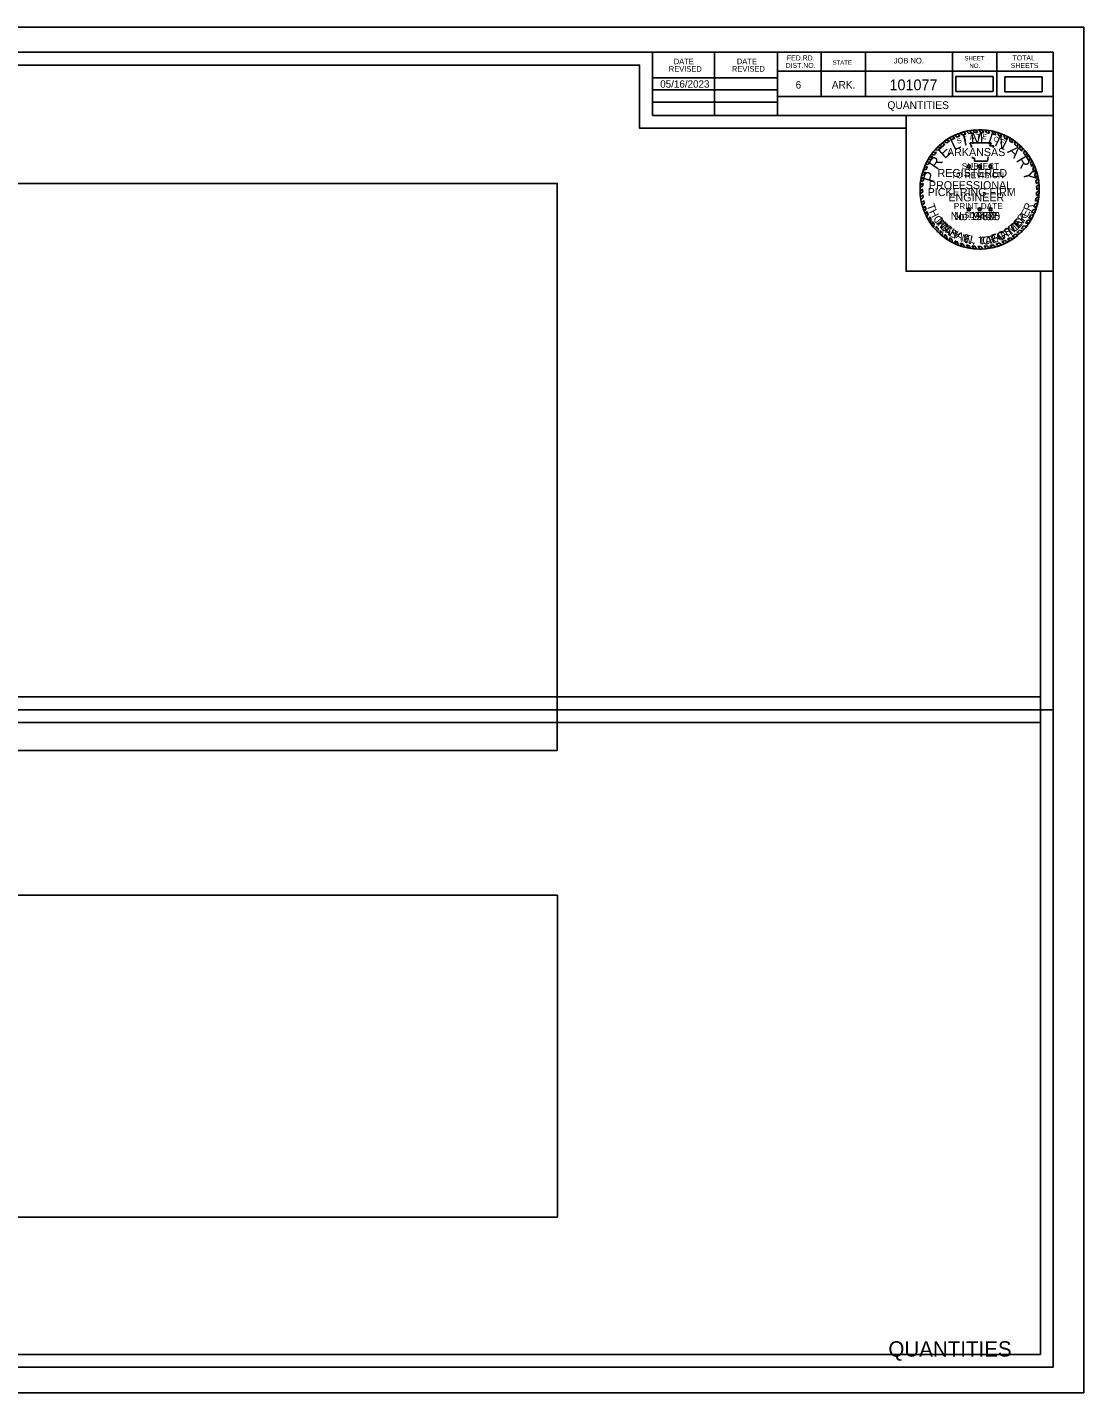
# Model space of a CAD drawing. Extents: x 1369655 to 1370989, y 380216 to 380430.
# Drawn here: x 1369823.5 to 1369988.6, y 380216.4 to 380429.8 of the extents above; entities that cross this region are included whole.
import ezdxf

# ---------------------------------------------------------------- set-up
doc = ezdxf.new("R2010")
doc.units = 0
for name, color, linetype in [('Default', 7, 'Continuous'), ('R_Border', 7, 'Continuous'), ('R_Border Notes', 7, 'Continuous'), ('R_Border Plan-Plan', 7, 'Continuous'), ('R_Border Title', 7, 'Continuous'), ('R_No Plot', 7, 'Continuous'), ('R_Revision Date Text', 7, 'Continuous'), ('STAMP_PE_CRAFTON', 7, 'Continuous'), ('STAMP_PE_FOSTER', 7, 'Continuous'), ('STAMP_PE_SEAL-INFO', 7, 'Continuous'), ('STAMP_PE_TAEGTMEYER', 7, 'Continuous'), ('STAMP_PE_TXT', 7, 'Continuous'), ('STAMP_PRELIMINARY', 7, 'Continuous')]:
    doc.layers.add(name, color=color, linetype=linetype)

msp = doc.modelspace()

# ---------------------------------------------------------------- linework, layer by layer
at = {"layer": 'Default'}
for points in [[(1369968.59, 380419.74), (1369974.42, 380419.74), (1369974.42, 380422.05), (1369968.59, 380422.05)], [(1369976.26, 380419.69), (1369982.09, 380419.69), (1369982.09, 380422), (1369976.26, 380422)], [(1369745.17, 380316.79), (1369906.32, 380316.79), (1369906.32, 380405.38), (1369745.17, 380405.38)], [(1369746.53, 380243.85), (1369906.34, 380243.85), (1369906.34, 380294.16), (1369746.53, 380294.16)]]:
    msp.add_lwpolyline(points, close=True, dxfattribs=at)
at = {"layer": 'R_Border'}
for p, q in [((1369667.65, 380425.87), (1369983.83, 380425.87)), ((1369921.19, 380415.99), (1369921.19, 380425.87)), ((1369930.87, 380415.99), (1369930.87, 380425.87)), ((1369940.73, 380425.87), (1369940.73, 380415.99)), ((1369947.57, 380425.87), (1369947.57, 380418.93)), ((1369954.51, 380425.87), (1369954.51, 380418.93)), ((1369968.09, 380425.87), (1369968.09, 380418.93)), ((1369975.03, 380425.87), (1369975.03, 380418.93)), ((1369983.83, 380220.41), (1369983.83, 380425.87)), ((1369921.19, 380421.85), (1369940.73, 380421.85)), ((1369983.83, 380422.93), (1369940.73, 380422.93)), ((1369983.83, 380422.95), (1369983.83, 380422.95)), ((1369921.19, 380419.99), (1369940.73, 380419.99)), ((1369921.19, 380418.05), (1369940.73, 380418.05)), ((1369983.83, 380418.93), (1369940.73, 380418.93)), ((1369943.69, 380418.93), (1369983.83, 380418.93)), ((1369983.83, 380415.99), (1369921.19, 380415.99)), ((1369983.83, 380220.41), (1369667.65, 380220.41))]:
    msp.add_line(p, q, dxfattribs=at)
at = {"layer": 'R_Border Plan-Plan'}
msp.add_line((1369667.65, 380323.14), (1369983.83, 380323.14), dxfattribs=at)
at = {"layer": 'R_No Plot'}
for points in [[(1369655.25, 380429.76), (1369988.59, 380429.76), (1369988.59, 380216.42), (1369655.25, 380216.42)], [(1369981.83, 380325.14), (1369669.65, 380325.14), (1369669.65, 380423.87), (1369919.19, 380423.87), (1369919.19, 380413.99), (1369936.73, 380413.99), (1369960.83, 380413.99), (1369960.83, 380391.65), (1369981.83, 380391.65)], [(1369669.65, 380423.87), (1369919.19, 380423.87), (1369919.19, 380413.99), (1369936.73, 380413.99), (1369960.83, 380413.99), (1369960.83, 380391.65), (1369981.83, 380391.65), (1369981.83, 380222.41), (1369669.65, 380222.41)], [(1369960.83, 380415.99), (1369983.83, 380415.99), (1369983.83, 380391.65), (1369960.83, 380391.65)], [(1369669.65, 380321.14), (1369981.83, 380321.14), (1369981.83, 380222.41), (1369669.65, 380222.41)]]:
    msp.add_lwpolyline(points, close=True, dxfattribs=at)
at = {"layer": 'STAMP_PE_SEAL-INFO'}
for p, q in [((1369968.95, 380413.12), (1369969.24, 380412.79)), ((1369969.29, 380413.24), (1369969.67, 380412.94)), ((1369969.88, 380413.43), (1369970.17, 380413.08)), ((1369970.27, 380413.52), (1369970.63, 380413.18)), ((1369970.75, 380413.62), (1369971.05, 380413.25)), ((1369971.27, 380413.69), (1369971.55, 380413.31)), ((1369972.01, 380413.34), (1369971.69, 380413.73)), ((1369972.5, 380413.34), (1369972.22, 380413.75)), ((1369972.96, 380413.32), (1369972.7, 380413.75)), ((1369973.47, 380413.27), (1369973.18, 380413.71)), ((1369973.89, 380413.21), (1369973.64, 380413.66)), ((1369974.46, 380413.09), (1369974.28, 380413.55)), ((1369974.86, 380412.98), (1369974.7, 380413.45)), ((1369975.31, 380412.83), (1369975.17, 380413.31)), ((1369975.73, 380412.67), (1369975.58, 380413.17)), ((1369976.19, 380412.47), (1369976.09, 380412.96)), ((1369965.7, 380410.98), (1369966.24, 380410.93)), ((1369966.03, 380411.3), (1369966.49, 380411.16)), ((1369966.37, 380411.6), (1369966.9, 380411.5)), ((1369966.75, 380411.93), (1369967.21, 380411.72)), ((1369967.17, 380412.19), (1369967.61, 380411.99)), ((1369967.56, 380412.44), (1369967.99, 380412.21)), ((1369968.01, 380412.69), (1369968.47, 380412.46)), ((1369968.44, 380412.9), (1369968.83, 380412.62)), ((1369970.81, 380411.72), (1369974.15, 380411.72)), ((1369970.93, 380411.41), (1369970.81, 380411.72)), ((1369971.03, 380411.12), (1369970.93, 380411.41)), ((1369971.04, 380411), (1369971.03, 380411.12)), ((1369974.15, 380411.72), (1369973.93, 380411.23)), ((1369973.93, 380411.23), (1369974.56, 380411.23)), ((1369974.56, 380411.23), (1369974.41, 380411)), ((1369976.63, 380412.24), (1369976.55, 380412.75)), ((1369977.02, 380412.01), (1369976.98, 380412.51)), ((1369977.46, 380411.72), (1369977.42, 380412.24)), ((1369977.82, 380411.46), (1369977.85, 380411.94)), ((1369978.26, 380411.09), (1369978.28, 380411.61)), ((1369978.58, 380410.79), (1369978.65, 380411.29)), ((1369978.93, 380410.42), (1369979, 380410.95)), ((1369964.04, 380408.68), (1369964.54, 380408.75)), ((1369964.27, 380409.11), (1369964.76, 380409.13)), ((1369964.51, 380409.51), (1369965.03, 380409.54)), ((1369964.75, 380409.85), (1369965.25, 380409.85)), ((1369965.03, 380410.22), (1369965.58, 380410.24)), ((1369965.37, 380410.63), (1369965.89, 380410.59)), ((1369971.23, 380409.29), (1369971.2, 380409.51)), ((1369971.54, 380409.29), (1369971.23, 380409.29)), ((1369971.54, 380408.86), (1369971.54, 380409.29)), ((1369973.57, 380408.86), (1369971.54, 380408.86)), ((1369973.59, 380409.2), (1369973.57, 380408.86)), ((1369973.67, 380409.51), (1369973.59, 380409.2)), ((1369979.21, 380410.1), (1369979.35, 380410.57)), ((1369979.53, 380409.69), (1369979.67, 380410.19)), ((1369979.75, 380409.37), (1369979.93, 380409.83)), ((1369980.06, 380408.87), (1369980.24, 380409.36)), ((1369980.26, 380408.51), (1369980.49, 380408.95)), ((1369963.25, 380406.54), (1369963.72, 380406.74)), ((1369963.36, 380406.95), (1369963.84, 380407.12)), ((1369963.52, 380407.45), (1369964, 380407.59)), ((1369963.67, 380407.86), (1369964.17, 380408.01)), ((1369963.85, 380408.29), (1369964.35, 380408.4)), ((1369980.49, 380408.02), (1369980.72, 380408.51)), ((1369980.63, 380407.69), (1369980.9, 380408.12)), ((1369980.83, 380407.14), (1369981.1, 380407.61)), ((1369980.93, 380406.77), (1369981.23, 380407.22)), ((1369981.07, 380406.21), (1369981.39, 380406.66)), ((1369963.44, 380404.98), (1369963.02, 380404.72)), ((1369963.42, 380404.49), (1369963.02, 380404.15)), ((1369963.47, 380405.4), (1369963.04, 380405.12)), ((1369963.53, 380405.84), (1369963.09, 380405.62)), ((1369963.62, 380406.3), (1369963.15, 380406.05)), ((1369981.14, 380405.83), (1369981.49, 380406.19)), ((1369981.2, 380405.32), (1369981.57, 380405.66)), ((1369981.23, 380404.91), (1369981.62, 380405.2)), ((1369981.25, 380404.39), (1369981.65, 380404.71)), ((1369963.43, 380404.08), (1369963.04, 380403.75)), ((1369963.46, 380403.58), (1369963.09, 380403.23)), ((1369963.51, 380403.15), (1369963.16, 380402.78)), ((1369963.59, 380402.69), (1369963.25, 380402.33)), ((1369963.68, 380402.28), (1369963.37, 380401.86)), ((1369980.95, 380402.14), (1369981.42, 380402.34)), ((1369981.06, 380402.59), (1369981.51, 380402.78)), ((1369981.15, 380403.09), (1369981.59, 380403.31)), ((1369981.2, 380403.48), (1369981.63, 380403.73)), ((1369981.24, 380403.98), (1369981.66, 380404.26)), ((1369963.81, 380401.83), (1369963.51, 380401.41)), ((1369963.95, 380401.41), (1369963.67, 380400.99)), ((1369964.12, 380400.98), (1369963.85, 380400.56)), ((1369964.29, 380400.6), (1369964.06, 380400.13)), ((1369980.29, 380400.41), (1369980.78, 380400.48)), ((1369980.45, 380400.75), (1369980.94, 380400.84)), ((1369980.67, 380401.26), (1369981.15, 380401.39)), ((1369980.8, 380401.64), (1369981.29, 380401.84)), ((1369964.52, 380400.14), (1369964.33, 380399.65)), ((1369964.76, 380399.73), (1369964.57, 380399.26)), ((1369964.96, 380399.42), (1369964.85, 380398.87)), ((1369965.24, 380399.03), (1369965.14, 380398.5)), ((1369965.54, 380398.65), (1369965.46, 380398.13)), ((1369965.85, 380398.32), (1369965.79, 380397.79)), ((1369978.56, 380398.05), (1369979, 380397.91)), ((1369978.82, 380398.31), (1369979.29, 380398.23)), ((1369979.2, 380398.74), (1369979.66, 380398.67)), ((1369979.51, 380399.14), (1369980.01, 380399.14)), ((1369979.85, 380399.63), (1369980.32, 380399.63)), ((1369980.02, 380399.91), (1369980.52, 380399.97)), ((1369966.17, 380397.99), (1369966.14, 380397.46)), ((1369966.51, 380397.68), (1369966.51, 380397.15)), ((1369966.87, 380397.38), (1369966.89, 380396.86)), ((1369967.21, 380397.13), (1369967.25, 380396.62)), ((1369967.64, 380396.85), (1369967.7, 380396.34)), ((1369967.99, 380396.65), (1369968.08, 380396.13)), ((1369968.47, 380396.4), (1369968.63, 380395.88)), ((1369968.84, 380396.23), (1369969.02, 380395.72)), ((1369969.34, 380396.04), (1369969.55, 380395.53)), ((1369969.75, 380395.9), (1369969.97, 380395.41)), ((1369974.89, 380395.89), (1369975.3, 380395.59)), ((1369975.38, 380396.05), (1369975.82, 380395.78)), ((1369975.8, 380396.22), (1369976.22, 380395.96)), ((1369976.26, 380396.43), (1369976.74, 380396.22)), ((1369976.67, 380396.64), (1369977.08, 380396.41)), ((1369977.08, 380396.89), (1369977.53, 380396.69)), ((1369977.42, 380397.11), (1369977.86, 380396.92)), ((1369977.88, 380397.46), (1369978.35, 380397.31)), ((1369978.16, 380397.68), (1369978.63, 380397.55)), ((1369970.25, 380395.76), (1369970.47, 380395.3)), ((1369970.65, 380395.68), (1369970.9, 380395.22)), ((1369971.15, 380395.6), (1369971.39, 380395.16)), ((1369971.59, 380395.55), (1369971.86, 380395.12)), ((1369972.07, 380395.52), (1369972.38, 380395.11)), ((1369972.53, 380395.52), (1369972.88, 380395.12)), ((1369973.05, 380395.55), (1369973.38, 380395.17)), ((1369973.49, 380395.59), (1369973.86, 380395.23)), ((1369973.93, 380395.66), (1369974.32, 380395.32)), ((1369974.43, 380395.77), (1369974.8, 380395.44))]:
    msp.add_line(p, q, dxfattribs=at)
for radius, start, end in [(9.32, 111.3124, 114.7026), (9.32, 105.2339, 109.0352), (8.91, 104.0352, 107.3615), (9.32, 99.7525, 102.7765), (8.91, 98.258, 101.0329), (9.32, 93.9381, 96.5517), (8.91, 92.1102, 95.0367), (9.32, 87.7298, 90.6707), (8.91, 85.9628, 88.9097), (9.32, 81.9732, 84.8236), (8.91, 79.9264, 82.696), (9.32, 75.3125, 77.9426), (8.91, 73.5575, 76.2314), (9.32, 69.6061, 72.3058), (9.32, 63.1329, 66.2704), (9.32, 135.4021, 138.3031), (8.91, 133.1331, 136.2562), (9.32, 129.7326, 132.5376), (8.91, 127.5297, 130.9683), (9.32, 123.6199, 126.5906), (8.91, 121.9746, 125.11), (9.32, 117.6544, 120.8099), (8.91, 115.6869, 119.1583), (8.91, 110.3086, 113.1659), (8.91, 67.6248, 70.504), (8.91, 61.1558, 64.3784), (9.32, 56.9003, 60.0942), (8.91, 54.9238, 58.2702), (8.91, 48.3016, 52.0395), (9.32, 50.3492, 53.7159), (9.32, 44.3405, 47.3929), (9.32, 152.864, 155.5189), (9.32, 147.0072, 149.899), (8.91, 151.0315, 153.573), (9.32, 141.6056, 144.4486), (8.91, 145.0197, 148.2104), (8.91, 139.301, 142.5873), (8.91, 42.2212, 45.5512), (8.91, 36.135, 39.5311), (9.32, 38.1247, 41.2316), (8.91, 29.9032, 33.6645), (9.32, 31.9614, 35.4294), (9.32, 25.9391, 29.0125), (9.32, 164.3068, 166.894), (9.32, 158.4077, 161.0701), (8.91, 162.4331, 165.0013), (8.91, 156.3402, 159.2319), (8.91, 23.7732, 27.2211), (8.91, 17.6802, 21.4251), (9.32, 19.9538, 23.3141), (8.91, 11.5444, 15.2364), (9.32, 13.8421, 17.4447), (9.32, 175.7409, 178.2066), (9.32, 170.0003, 172.6878), (8.91, 179.6454, 182.2633), (8.91, 173.73, 176.4734), (8.91, 167.9048, 170.9039), (8.91, 5.7599, 9.0606), (8.91, 359.7329, 3.0639), (9.32, 7.5852, 10.8621), (9.32, 1.7215, 4.7268), (9.32, 181.7251, 184.1626), (9.32, 187.4204, 190.1927), (9.32, 193.0369, 195.9973), (8.91, 185.4539, 188.234), (8.91, 191.2274, 193.9858), (8.91, 348.0778, 351.3435), (8.91, 353.8632, 357.1274), (9.32, 343.8925, 347.035), (9.32, 349.8305, 353.0885), (9.32, 355.7156, 358.9569), (9.32, 198.8967, 201.6281), (8.91, 196.9675, 199.8353), (9.32, 204.5479, 207.4328), (8.91, 202.7761, 205.4791), (8.91, 329.5549, 333.2076), (8.91, 335.6038, 339.1858), (9.32, 331.4037, 334.9332), (8.91, 341.777, 345.0925), (9.32, 337.3837, 340.9933), (9.32, 210.8636, 213.6571), (8.91, 208.7883, 211.7934), (9.32, 216.6115, 219.491), (8.91, 214.1838, 217.2747), (9.32, 222.48, 225.3801), (8.91, 220.3909, 223.3056), (8.91, 310.7744, 314.3161), (8.91, 316.6531, 320.3711), (9.32, 318.2846, 321.8043), (8.91, 323.5851, 327.4407), (9.32, 325.4405, 328.9872), (9.32, 228.3665, 231.348), (8.91, 226.2494, 229.2407), (8.91, 232.229, 234.9336), (9.32, 234.295, 236.9452), (8.91, 238.2223, 240.8353), (9.32, 240.1977, 242.8613), (8.91, 244.3204, 246.9486), (9.32, 246.576, 249.1558), (8.91, 250.3491, 253.1216), (8.91, 286.6423, 289.9783), (8.91, 292.8745, 296.1185), (9.32, 294.6481, 298.2166), (8.91, 299.0768, 302.1724), (9.32, 300.621, 303.8703), (8.91, 304.823, 308.5143), (9.32, 306.3721, 310.208), (9.32, 312.4518, 315.6633), (9.32, 252.5967, 255.3252), (8.91, 256.505, 259.1192), (9.32, 258.4433, 261.1398), (8.91, 262.3783, 265.2012), (9.32, 264.1978, 267.1009), (8.91, 268.3215, 271.277), (9.32, 270.2548, 273.3361), (8.91, 274.6157, 277.4486), (9.32, 276.4239, 279.4357), (8.91, 280.3459, 283.5814), (9.32, 282.3199, 285.3702), (9.32, 288.5709, 291.9733)]:
    msp.add_arc((1369972.33, 380404.43), radius, start, end, dxfattribs=at)
at = {"layer": 'STAMP_PE_TXT'}
for p, q in [((1369970.51, 380408), (1369970.31, 380408.15)), ((1369970.31, 380408.15), (1369970.56, 380408.15)), ((1369970.44, 380407.77), (1369970.51, 380408)), ((1369970.64, 380407.91), (1369970.44, 380407.77)), ((1369970.56, 380408.15), (1369970.64, 380408.38)), ((1369970.64, 380408.38), (1369970.71, 380408.15)), ((1369970.83, 380407.77), (1369970.64, 380407.91)), ((1369970.71, 380408.15), (1369970.96, 380408.15)), ((1369970.96, 380408.15), (1369970.76, 380408)), ((1369970.76, 380408), (1369970.83, 380407.77)), ((1369972.21, 380408), (1369972.01, 380408.15)), ((1369972.01, 380408.15), (1369972.26, 380408.15)), ((1369972.14, 380407.77), (1369972.21, 380408)), ((1369972.33, 380407.91), (1369972.14, 380407.77)), ((1369972.26, 380408.15), (1369972.33, 380408.38)), ((1369972.33, 380408.38), (1369972.41, 380408.15)), ((1369972.53, 380407.77), (1369972.33, 380407.91)), ((1369972.41, 380408.15), (1369972.65, 380408.15)), ((1369972.65, 380408.15), (1369972.46, 380408)), ((1369972.46, 380408), (1369972.53, 380407.77)), ((1369973.91, 380408), (1369973.71, 380408.15)), ((1369973.71, 380408.15), (1369973.96, 380408.15)), ((1369973.83, 380407.77), (1369973.91, 380408)), ((1369974.03, 380407.91), (1369973.83, 380407.77)), ((1369973.96, 380408.15), (1369974.03, 380408.38)), ((1369974.03, 380408.38), (1369974.11, 380408.15)), ((1369974.23, 380407.77), (1369974.03, 380407.91)), ((1369974.11, 380408.15), (1369974.35, 380408.15)), ((1369974.35, 380408.15), (1369974.15, 380408)), ((1369974.15, 380408), (1369974.23, 380407.77)), ((1369970.51, 380401.29), (1369970.31, 380401.44)), ((1369970.31, 380401.44), (1369970.56, 380401.44)), ((1369970.44, 380401.06), (1369970.51, 380401.29)), ((1369970.64, 380401.21), (1369970.44, 380401.06)), ((1369970.56, 380401.44), (1369970.64, 380401.67)), ((1369970.64, 380401.67), (1369970.71, 380401.44)), ((1369970.83, 380401.06), (1369970.64, 380401.21)), ((1369970.71, 380401.44), (1369970.96, 380401.44)), ((1369970.96, 380401.44), (1369970.76, 380401.29)), ((1369970.76, 380401.29), (1369970.83, 380401.06)), ((1369972.21, 380401.29), (1369972.01, 380401.44)), ((1369972.01, 380401.44), (1369972.26, 380401.44)), ((1369972.14, 380401.06), (1369972.21, 380401.29)), ((1369972.33, 380401.21), (1369972.14, 380401.06)), ((1369972.26, 380401.44), (1369972.33, 380401.67)), ((1369972.33, 380401.67), (1369972.41, 380401.44)), ((1369972.53, 380401.06), (1369972.33, 380401.21)), ((1369972.41, 380401.44), (1369972.65, 380401.44)), ((1369972.65, 380401.44), (1369972.46, 380401.29)), ((1369972.46, 380401.29), (1369972.53, 380401.06)), ((1369973.91, 380401.29), (1369973.71, 380401.44)), ((1369973.71, 380401.44), (1369973.96, 380401.44)), ((1369973.83, 380401.06), (1369973.91, 380401.29)), ((1369974.03, 380401.21), (1369973.83, 380401.06)), ((1369973.96, 380401.44), (1369974.03, 380401.67)), ((1369974.03, 380401.67), (1369974.11, 380401.44)), ((1369974.23, 380401.06), (1369974.03, 380401.21)), ((1369974.11, 380401.44), (1369974.35, 380401.44)), ((1369974.35, 380401.44), (1369974.15, 380401.29)), ((1369974.15, 380401.29), (1369974.23, 380401.06))]:
    msp.add_line(p, q, dxfattribs=at)
at = {"layer": 'STAMP_PRELIMINARY'}
msp.add_circle((1369972.33, 380404.43), 9.32, dxfattribs=at)

# ---------------------------------------------------------------- texts
at = {"layer": 'R_Border'}
for s, height, p in [('REVISED', 0.879, (1369923.75, 380422.82)), ('DATE', 0.879, (1369924.53, 380424)), ('REVISED', 0.879, (1369933.61, 380422.82)), ('DATE', 0.879, (1369934.39, 380424)), ('DIST.NO.', 0.782, (1369942.01, 380423.41)), ('FED.RD.', 0.782, (1369942.21, 380424.59)), ('STATE', 0.684, (1369949.33, 380423.91)), ('JOB NO.', 0.879, (1369958.91, 380424.11)), ('SHEET', 0.684, (1369969.95, 380424.59)), ('NO.', 0.684, (1369970.73, 380423.41)), ('SHEETS', 0.782, (1369977.19, 380423.41)), ('TOTAL', 0.782, (1369977.47, 380424.59)), ('6', 1.17, (1369943.57, 380420.19)), ('ARK.', 1.172, (1369949.23, 380420.19))]:
    msp.add_text(s, height=height, dxfattribs=at).set_placement(p)
at = {"layer": 'R_Border Notes'}
for s, height, p in [('101077', 1.68, (1369958.24, 380419.93)), ('QUANTITIES', 1.2, (1369957.91, 380417.01))]:
    msp.add_text(s, height=height, dxfattribs=at).set_placement(p)
at = {"layer": 'R_Border Title'}
msp.add_text('QUANTITIES', height=2.4, dxfattribs=at).set_placement((1369958.07, 380222.06))
at = {"layer": 'R_Revision Date Text'}
msp.add_text('05/16/2023', height=1.15, dxfattribs=at).set_placement((1369922.41, 380420.33))
at = {"layer": 'STAMP_PE_CRAFTON'}
msp.add_text('No. 12370', height=1.25, dxfattribs=at).set_placement((1369967.8, 380399.63))
for s, rotation, p in [('T', 310.7442, (1369965.3, 380399.33)), ('O', 317.6422, (1369965.97, 380398.52)), ('N', 324.4537, (1369966.81, 380397.73)), ('Y', 331.1686, (1369967.85, 380397.02)), ('F', 28.7821, (1369975.99, 380396.56)), ('T', 34.1136, (1369976.91, 380397.07)), ('O', 41.8391, (1369977.77, 380397.67)), ('N', 49.2411, (1369978.62, 380398.45)), ('N', 347.4752, (1369969.9, 380396.1)), ('.', 356.8926, (1369971.13, 380395.82)), ('C', 6.0117, (1369972.81, 380395.77)), ('R', 14.8189, (1369973.9, 380395.89)), ('A', 20.5125, (1369975.01, 380396.19))]:
    msp.add_text(s, height=1.25, rotation=rotation, dxfattribs=at).set_placement(p)
at = {"layer": 'STAMP_PE_FOSTER'}
msp.add_text('No. 9402', height=1.25, dxfattribs=at).set_placement((1369968.32, 380399.63))
for s, rotation, p in [('R', 54.5031, (1369979.06, 380399.24)), ('M', 308.339, (1369965.45, 380399.45)), ('I', 314.1842, (1369966.25, 380398.51)), ('C', 319.8733, (1369966.6, 380398.16)), ('H', 327.7235, (1369967.53, 380397.42)), ('S', 31.7234, (1369976.52, 380397.04)), ('T', 39.4194, (1369977.48, 380397.67)), ('E', 46.9613, (1369978.33, 380398.42)), ('A', 335.7276, (1369968.51, 380396.84)), ('E', 343.5779, (1369969.65, 380396.37)), ('L', 350.8115, (1369970.71, 380396.1)), ('L', 1.2666, (1369972.25, 380395.94)), ('.', 6.8035, (1369973.29, 380396)), ('F', 15.8691, (1369974.37, 380396.18)), ('O', 23.719, (1369975.41, 380396.51))]:
    msp.add_text(s, height=1.2, rotation=rotation, dxfattribs=at).set_placement(p)
at = {"layer": 'STAMP_PE_TAEGTMEYER'}
for s, rotation, p in [('T', 289.646, (1369964.03, 380401.94)), ('R', 69.57, (1369980.28, 380400.94)), ('H', 296.7339, (1369964.39, 380400.96)), ('O', 303.7708, (1369964.98, 380399.85)), ('Y', 53.9986, (1369979.11, 380399.02)), ('E', 63.0984, (1369979.78, 380399.96)), ('M', 314.2033, (1369965.64, 380398.9)), ('A', 321.0594, (1369966.6, 380397.93)), ('S', 327.8239, (1369967.42, 380397.29)), ('T', 31.466, (1369976.43, 380396.78)), ('M', 39.3, (1369977.33, 380397.33)), ('E', 46.8094, (1369978.37, 380398.21)), ('N', 344.2727, (1369969.32, 380396.28)), ('.', 350.6464, (1369970.53, 380395.95)), ('T', 3.0061, (1369972.2, 380395.75)), ('A', 8.9826, (1369973.24, 380395.81)), ('E', 17.6836, (1369974.28, 380395.96)), ('G', 23.3052, (1369975.33, 380396.29))]:
    msp.add_text(s, height=1.25, rotation=rotation, dxfattribs=at).set_placement(p)
msp.add_text('No. 19605', height=1.25, dxfattribs=at).set_placement((1369967.8, 380399.63))
at = {"layer": 'STAMP_PE_TXT'}
for s, rotation, p in [('A', 9.0679, (1369970.82, 380412.16)), ('T', 1.8248, (1369971.8, 380412.29)), ('E', 355.2002, (1369972.71, 380412.3)), ('S', 23.5541, (1369968.93, 380411.53)), ('T', 16.311, (1369969.86, 380411.91)), ('O', 342.2506, (1369974.44, 380412.02)), ('F', 335.0075, (1369975.41, 380411.68))]:
    msp.add_text(s, height=0.781, rotation=rotation, dxfattribs=at).set_placement(p)
for s, p in [('ARKANSAS', (1369967.23, 380409.64)), ('REGISTERED', (1369965.75, 380406.37)), ('PROFESSIONAL', (1369964.4, 380404.47)), ('ENGINEER', (1369967.44, 380402.57))]:
    msp.add_text(s, height=1.25, dxfattribs=at).set_placement(p)
at = {"layer": 'STAMP_PRELIMINARY'}
for s, rotation, p in [('I', 12.5248, (1369969.87, 380411.22)), ('M', 3.1074, (1369970.97, 380411.53)), ('I', 342.3164, (1369973.44, 380411.59)), ('E', 42.3578, (1369966.86, 380409.13)), ('L', 25.513, (1369968.34, 380410.46)), ('N', 333.9382, (1369974.54, 380411.32)), ('A', 315.6579, (1369976.58, 380410.29)), ('R', 56.2292, (1369965.7, 380407.39)), ('R', 301.3831, (1369977.95, 380408.98)), ('P', 73.913, (1369965.16, 380405.37)), ('Y', 283.2593, (1369979.04, 380407.19))]:
    msp.add_text(s, height=1.8, rotation=rotation, dxfattribs=at).set_placement(p)
for s, height, p in [('TO REVISION', 0.96, (1369967.87, 380406.19)), ('SUBJECT', 0.96, (1369969.53, 380407.58)), ('PICKERING FIRM', 1.25, (1369964.21, 380403.39)), ('PRINT DATE', 0.96, (1369968.29, 380401.35)), ('$DATE$', 0.96, (1369969.97, 380399.96))]:
    msp.add_text(s, height=height, dxfattribs=at).set_placement(p)

doc.saveas('drawing.dxf')
